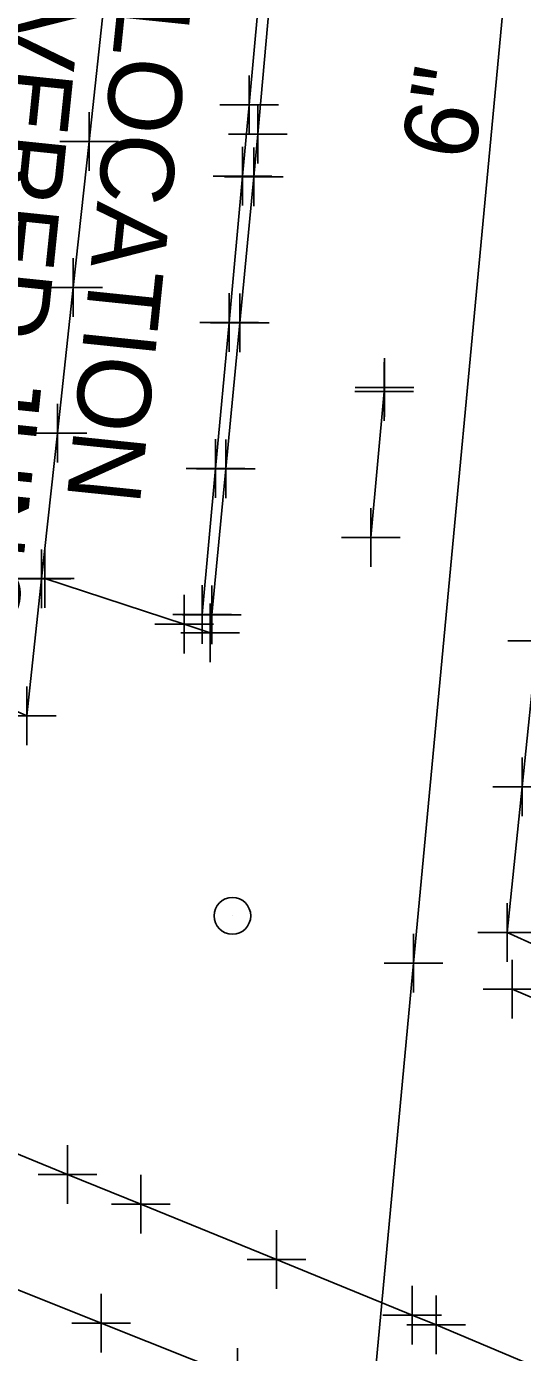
# Model space of a CAD drawing. Extents: x 0 to 1944463, y 0 to 420651.
# Drawn here: x 1942710.7 to 1942744.5, y 417858.9 to 417949.3 of the extents above; entities that cross this region are included whole.
import ezdxf

# ---------------------------------------------------------------- set-up
doc = ezdxf.new("R2010")
doc.units = 0
for name, color, linetype in [('SUR - DRG - Storm Sewer Text', 7, 'Continuous'), ('SUR - DTM - Breaklines', 7, 'Continuous'), ('SUR - DTM - Breaklines - Points - Locators', 7, 'Continuous'), ('SUR - DTM - Spot Points - Locators', 7, 'Continuous'), ('SUR - TR-CTRL - Pavement Marking', 7, 'Continuous'), ('SUR - TR-CTRL - Pavement Marking - Points - Locators', 7, 'Continuous'), ('SUR - UTL - Water', 7, 'Continuous'), ('SUR - UTL - Water - Points - Locators', 7, 'Continuous'), ('SUR - UTL - Water Text', 7, 'Continuous')]:
    doc.layers.add(name, color=color, linetype=linetype)

msp = doc.modelspace()

# ---------------------------------------------------------------- linework, layer by layer
at = {"layer": 'SUR - DTM - Breaklines'}
for points in [[(1942691.985, 417879.124), (1942701.418, 417875.806), (1942704.218, 417874.821), (1942713.477, 417871.044), (1942718.474, 417869.005), (1942727.733, 417865.227), (1942736.992, 417861.45), (1942738.626, 417860.783), (1942747.84, 417856.896), (1942751.278, 417855.446), (1942760.405, 417851.361), (1942769.533, 417847.277), (1942772.273, 417846.051)], [(1942706.496, 417864.602), (1942715.785, 417860.899), (1942725.074, 417857.195), (1942728.142, 417855.972), (1942737.3, 417851.955), (1942746.457, 417847.938), (1942755.615, 417843.922), (1942764.773, 417839.905), (1942767.692, 417838.624), (1942776.578, 417834.037), (1942785.464, 417829.45), (1942794.35, 417824.864), (1942803.236, 417820.277), (1942812.122, 417815.69), (1942818.635, 417812.328), (1942827.298, 417807.331), (1942835.96, 417802.335), (1942844.622, 417797.339), (1942853.285, 417792.343), (1942860.379, 417788.251), (1942868.814, 417782.88), (1942877.25, 417777.509), (1942885.685, 417772.138), (1942894.12, 417766.767)]]:
    msp.add_lwpolyline(points, dxfattribs=at)
at = {"layer": 'SUR - DTM - Breaklines - Points - Locators'}
for p, q in [((1942713.477, 417871.044), (1942713.477, 417873.044)), ((1942713.477, 417871.044), (1942711.477, 417871.044)), ((1942713.477, 417871.044), (1942715.477, 417871.044)), ((1942713.477, 417871.044), (1942713.477, 417869.044)), ((1942718.474, 417869.005), (1942718.474, 417871.005)), ((1942718.474, 417869.005), (1942716.474, 417869.005)), ((1942718.474, 417869.005), (1942720.474, 417869.005)), ((1942718.474, 417869.005), (1942718.474, 417867.005)), ((1942727.733, 417865.227), (1942727.733, 417867.227)), ((1942727.733, 417865.227), (1942725.733, 417865.227)), ((1942727.733, 417865.227), (1942729.733, 417865.227)), ((1942727.733, 417865.227), (1942727.733, 417863.227)), ((1942715.785, 417860.899), (1942715.785, 417862.899)), ((1942736.992, 417861.45), (1942736.992, 417863.45)), ((1942738.626, 417860.783), (1942738.626, 417862.783)), ((1942736.992, 417861.45), (1942734.992, 417861.45)), ((1942736.992, 417861.45), (1942738.992, 417861.45)), ((1942736.992, 417861.45), (1942736.992, 417859.45)), ((1942715.785, 417860.899), (1942713.785, 417860.899)), ((1942715.785, 417860.899), (1942717.785, 417860.899)), ((1942715.785, 417860.899), (1942715.785, 417858.899)), ((1942738.626, 417860.783), (1942736.626, 417860.783)), ((1942738.626, 417860.783), (1942740.626, 417860.783)), ((1942738.626, 417860.783), (1942738.626, 417858.783)), ((1942725.074, 417857.195), (1942725.074, 417859.195))]:
    msp.add_line(p, q, dxfattribs=at)
at = {"layer": 'SUR - DTM - Spot Points - Locators'}
msp.add_line((1942724.74, 417888.66), (1942724.74, 417888.66), dxfattribs=at)
msp.add_circle((1942724.729, 417888.671), 1.25, dxfattribs=at)
at = {"layer": 'SUR - TR-CTRL - Pavement Marking'}
for points in [[(1942722.67, 417909.219), (1942723.585, 417919.177), (1942724.5, 417929.135), (1942725.415, 417939.093), (1942725.863, 417943.963), (1942726.778, 417953.921), (1942727.693, 417963.88), (1942728.608, 417973.838), (1942729.056, 417978.708), (1942729.971, 417988.666), (1942730.886, 417998.624), (1942731.801, 418008.582), (1942732.63, 418017.598), (1942733.545, 418027.556), (1942734.264, 418035.38)], [(1942723.328, 417909.191), (1942724.28, 417919.146), (1942725.232, 417929.1), (1942726.184, 417939.055), (1942726.462, 417941.958), (1942727.358, 417951.918), (1942728.254, 417961.877), (1942729.151, 417971.837), (1942729.577, 417976.571), (1942730.507, 417986.527), (1942731.438, 417996.484), (1942732.369, 418006.44), (1942733.3, 418016.397), (1942734.23, 418026.354), (1942735.065, 418035.287)], [(1942720.337, 417998.196), (1942719.42, 417988.238), (1942718.503, 417978.28), (1942717.586, 417968.322), (1942716.668, 417958.364), (1942716.027, 417951.404), (1942714.949, 417941.463), (1942713.87, 417931.521), (1942712.791, 417921.579), (1942711.713, 417911.638), (1942710.701, 417902.312), (1942701.559, 417906.365), (1942692.417, 417910.417), (1942683.275, 417914.47), (1942674.133, 417918.522), (1942665.998, 417922.128)], [(1942799.725, 417861.277), (1942790.736, 417865.658), (1942781.747, 417870.039), (1942775.062, 417873.297), (1942765.944, 417877.403), (1942756.825, 417881.508), (1942747.707, 417885.614), (1942743.465, 417887.524), (1942744.493, 417897.471), (1942745.521, 417907.418), (1942746.549, 417917.365), (1942747.578, 417927.312), (1942748.606, 417937.259), (1942749.634, 417947.206), (1942750.63, 417956.84)], [(1942734.18, 417914.465), (1942735.085, 417924.424), (1942735.109, 417924.687)], [(1942711.936, 417911.681), (1942721.432, 417908.546), (1942723.209, 417907.96)], [(1942743.821, 417883.68), (1942753.017, 417879.751), (1942762.213, 417875.823), (1942770.046, 417872.476), (1942779.106, 417868.245), (1942788.166, 417864.013), (1942790.281, 417863.025), (1942799.195, 417858.492), (1942808.108, 417853.959), (1942814.469, 417850.724), (1942823.271, 417845.977), (1942832.073, 417841.23), (1942837.137, 417838.5), (1942845.787, 417833.481), (1942854.436, 417828.462), (1942863.086, 417823.444), (1942865.149, 417822.246), (1942873.606, 417816.91), (1942882.063, 417811.573), (1942888.586, 417807.457), (1942896.946, 417801.969)]]:
    msp.add_lwpolyline(points, dxfattribs=at)
at = {"layer": 'SUR - TR-CTRL - Pavement Marking - Points - Locators'}
for p, q in [((1942725.863, 417943.963), (1942725.863, 417945.963)), ((1942714.949, 417941.463), (1942714.949, 417943.463)), ((1942725.863, 417943.963), (1942723.863, 417943.963)), ((1942725.863, 417943.963), (1942727.863, 417943.963)), ((1942725.863, 417943.963), (1942725.863, 417941.963)), ((1942726.462, 417941.958), (1942726.462, 417943.958)), ((1942726.462, 417941.958), (1942724.462, 417941.958)), ((1942726.462, 417941.958), (1942728.462, 417941.958)), ((1942726.462, 417941.958), (1942726.462, 417939.958)), ((1942714.949, 417941.463), (1942712.949, 417941.463)), ((1942714.949, 417941.463), (1942716.949, 417941.463)), ((1942714.949, 417941.463), (1942714.949, 417939.463)), ((1942725.415, 417939.093), (1942725.415, 417941.093)), ((1942726.184, 417939.055), (1942726.184, 417941.055)), ((1942725.415, 417939.093), (1942723.415, 417939.093)), ((1942726.184, 417939.055), (1942724.184, 417939.055)), ((1942725.415, 417939.093), (1942727.415, 417939.093)), ((1942725.415, 417939.093), (1942725.415, 417937.093)), ((1942726.184, 417939.055), (1942728.184, 417939.055)), ((1942726.184, 417939.055), (1942726.184, 417937.055)), ((1942713.87, 417931.521), (1942713.87, 417933.521)), ((1942713.87, 417931.521), (1942711.87, 417931.521)), ((1942713.87, 417931.521), (1942715.87, 417931.521)), ((1942713.87, 417931.521), (1942713.87, 417929.521)), ((1942724.5, 417929.135), (1942724.5, 417931.135)), ((1942725.232, 417929.1), (1942725.232, 417931.1)), ((1942724.5, 417929.135), (1942722.5, 417929.135)), ((1942725.232, 417929.1), (1942723.232, 417929.1)), ((1942724.5, 417929.135), (1942726.5, 417929.135)), ((1942724.5, 417929.135), (1942724.5, 417927.135)), ((1942725.232, 417929.1), (1942727.232, 417929.1)), ((1942725.232, 417929.1), (1942725.232, 417927.1)), ((1942735.085, 417924.424), (1942735.085, 417926.424)), ((1942735.109, 417924.687), (1942735.109, 417926.687)), ((1942735.085, 417924.424), (1942733.085, 417924.424)), ((1942735.109, 417924.687), (1942733.109, 417924.687)), ((1942735.085, 417924.424), (1942737.085, 417924.424)), ((1942735.085, 417924.424), (1942735.085, 417922.424)), ((1942735.109, 417924.687), (1942737.109, 417924.687)), ((1942735.109, 417924.687), (1942735.109, 417922.687)), ((1942712.791, 417921.579), (1942712.791, 417923.579)), ((1942712.791, 417921.579), (1942710.791, 417921.579)), ((1942712.791, 417921.579), (1942714.791, 417921.579)), ((1942712.791, 417921.579), (1942712.791, 417919.579)), ((1942723.585, 417919.177), (1942723.585, 417921.177)), ((1942724.28, 417919.146), (1942724.28, 417921.146)), ((1942723.585, 417919.177), (1942721.585, 417919.177)), ((1942724.28, 417919.146), (1942722.28, 417919.146)), ((1942723.585, 417919.177), (1942725.585, 417919.177)), ((1942723.585, 417919.177), (1942723.585, 417917.177)), ((1942724.28, 417919.146), (1942726.28, 417919.146)), ((1942724.28, 417919.146), (1942724.28, 417917.146)), ((1942734.18, 417914.465), (1942734.18, 417916.465)), ((1942734.18, 417914.465), (1942732.18, 417914.465)), ((1942734.18, 417914.465), (1942736.18, 417914.465)), ((1942734.18, 417914.465), (1942734.18, 417912.465)), ((1942711.713, 417911.638), (1942711.713, 417913.638)), ((1942711.936, 417911.681), (1942711.936, 417913.681)), ((1942711.713, 417911.638), (1942709.713, 417911.638)), ((1942711.936, 417911.681), (1942709.936, 417911.681)), ((1942711.713, 417911.638), (1942713.713, 417911.638)), ((1942711.713, 417911.638), (1942711.713, 417909.638)), ((1942711.936, 417911.681), (1942713.936, 417911.681)), ((1942711.936, 417911.681), (1942711.936, 417909.681)), ((1942722.67, 417909.219), (1942722.67, 417911.219)), ((1942723.328, 417909.191), (1942723.328, 417911.191)), ((1942721.432, 417908.546), (1942721.432, 417910.546)), ((1942723.209, 417907.96), (1942723.209, 417909.96)), ((1942722.67, 417909.219), (1942720.67, 417909.219)), ((1942723.328, 417909.191), (1942721.328, 417909.191)), ((1942722.67, 417909.219), (1942724.67, 417909.219)), ((1942722.67, 417909.219), (1942722.67, 417907.219)), ((1942723.328, 417909.191), (1942725.328, 417909.191)), ((1942723.328, 417909.191), (1942723.328, 417907.191)), ((1942721.432, 417908.546), (1942719.432, 417908.546)), ((1942721.432, 417908.546), (1942723.432, 417908.546)), ((1942721.432, 417908.546), (1942721.432, 417906.546)), ((1942723.209, 417907.96), (1942721.209, 417907.96)), ((1942723.209, 417907.96), (1942725.209, 417907.96)), ((1942723.209, 417907.96), (1942723.209, 417905.96)), ((1942745.521, 417907.418), (1942743.521, 417907.418)), ((1942710.701, 417902.312), (1942710.701, 417904.312)), ((1942710.701, 417902.312), (1942708.701, 417902.312)), ((1942710.701, 417902.312), (1942712.701, 417902.312)), ((1942710.701, 417902.312), (1942710.701, 417900.312)), ((1942744.493, 417897.471), (1942744.493, 417899.471)), ((1942744.493, 417897.471), (1942742.493, 417897.471)), ((1942744.493, 417897.471), (1942746.493, 417897.471)), ((1942744.493, 417897.471), (1942744.493, 417895.471)), ((1942743.465, 417887.524), (1942743.465, 417889.524)), ((1942743.465, 417887.524), (1942741.465, 417887.524)), ((1942743.465, 417887.524), (1942745.465, 417887.524)), ((1942743.465, 417887.524), (1942743.465, 417885.524)), ((1942743.821, 417883.68), (1942743.821, 417885.68)), ((1942743.821, 417883.68), (1942741.821, 417883.68)), ((1942743.821, 417883.68), (1942745.821, 417883.68)), ((1942743.821, 417883.68), (1942743.821, 417881.68))]:
    msp.add_line(p, q, dxfattribs=at)
at = {"layer": 'SUR - UTL - Water'}
msp.add_lwpolyline([(1942721.71, 417720.78), (1942729.22, 417801.1), (1942737.09, 417885.44), (1942743.84, 417957.42), (1942750.2, 418026.1), (1942756.89, 418096.95)], dxfattribs=at)
at = {"layer": 'SUR - UTL - Water - Points - Locators'}
for q in [(1942737.09, 417887.44), (1942737.09, 417887.44), (1942735.09, 417885.44), (1942735.09, 417885.44), (1942739.09, 417885.44), (1942737.09, 417883.44), (1942739.09, 417885.44), (1942737.09, 417883.44)]:
    msp.add_line((1942737.09, 417885.44), q, dxfattribs=at)

# ---------------------------------------------------------------- texts
at = {"layer": 'SUR - DRG - Storm Sewer Text'}
for s, p in [('INACCESSIBLE COVERED JUNCTION', (1942715.602, 418011.359)), ('APPROX. LOCATION', (1942720.169, 417982.528))]:
    msp.add_text(s, height=4.99999, rotation=264.11419, dxfattribs=at).set_placement(p)
at = {"layer": 'SUR - UTL - Water Text'}
msp.add_text('6"', height=5, rotation=80.54328, dxfattribs=at).set_placement((1942741.138, 417940.018))

doc.saveas('drawing.dxf')
